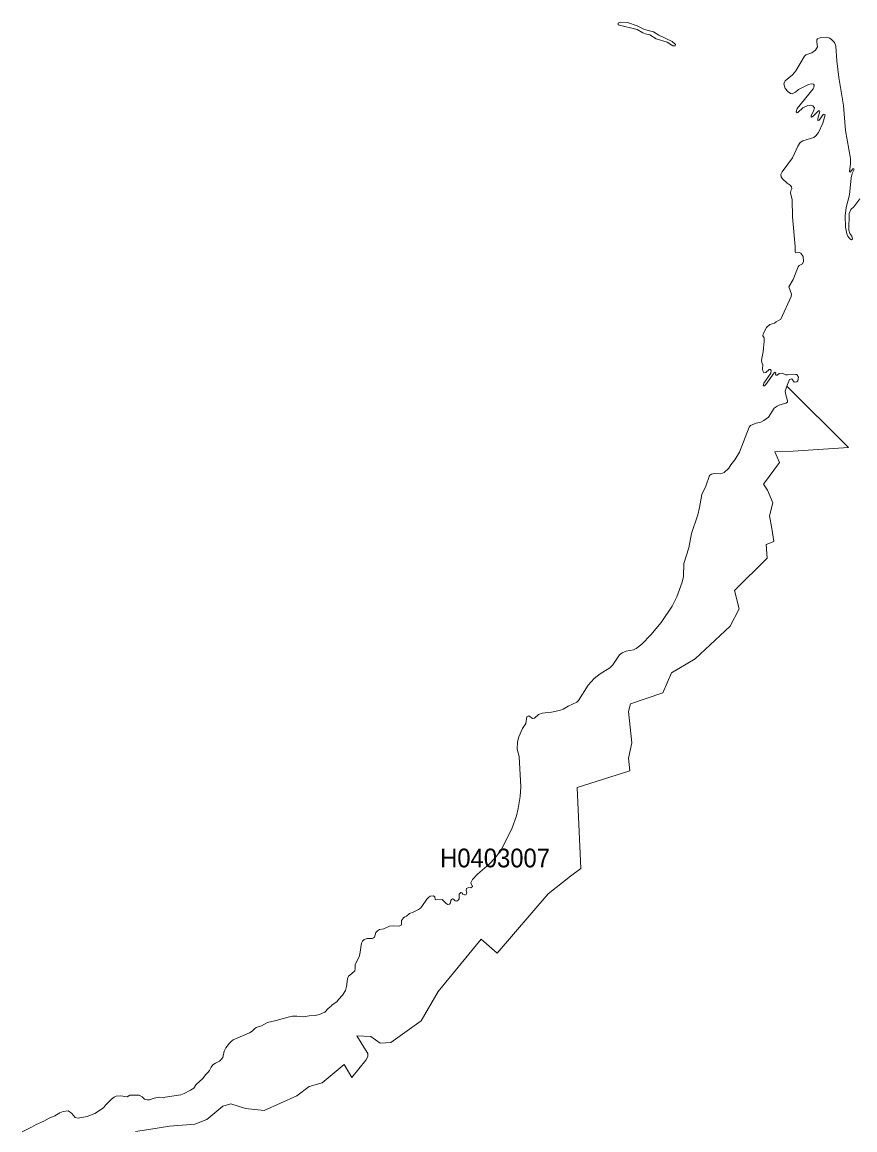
# Model space of a CAD drawing. Extents: x 369010 to 739155, y 6377141 to 6616555.
# Drawn here: x 410311 to 414756, y 6494241 to 6500155 of the extents above; entities that cross this region are included whole.
import ezdxf
from ezdxf.enums import TextEntityAlignment as Align

# ---------------------------------------------------------------- set-up
doc = ezdxf.new("R2010")
doc.units = 0
doc.header["$LTSCALE"] = 40
doc.layers.add('1', color=7, linetype='Continuous', lineweight=13)
doc.layers.add('2', color=7, linetype='Continuous')

msp = doc.modelspace()

# ---------------------------------------------------------------- linework, layer by layer
at = {"layer": '1'}
msp.add_lwpolyline([(413797.24, 6500028.2), (413799.73, 6500034.66), (413781.85, 6500051.7), (413709.36, 6500085.47), (413682.05, 6500103.18), (413633.73, 6500116.09), (413593.34, 6500135.45), (413542.53, 6500152.5), (413505.46, 6500154.81), (413491.89, 6500149.19), (413493.38, 6500140.41), (413593.34, 6500116.09), (413624.79, 6500097.55), (413644.15, 6500090.43), (413661.03, 6500087.95), (413694.96, 6500065.44), (413753.72, 6500047.57), (413785.16, 6500027.54)], close=True, dxfattribs=at)
for points in [[(414783.32, 6499212.27), (414751.21, 6499169.57), (414735.32, 6499154.34), (414726.71, 6499132.49), (414724.73, 6499044.12), (414730.02, 6499026.41), (414739.46, 6499012.67), (414744.42, 6498995.62), (414739.13, 6498991.98), (414730.35, 6498998.77), (414719.1, 6499012.67), (414714.14, 6499024.75), (414707.02, 6499060), (414704.37, 6499120.74), (414710.49, 6499166.09), (414727.71, 6499232.13), (414737.64, 6499322.82), (414742.93, 6499347.48), (414752.37, 6499367.84), (414750.38, 6499371.32), (414746.41, 6499371.15), (414731.51, 6499354.6), (414728.53, 6499356.42), (414733.5, 6499400.61), (414733.17, 6499427.09), (414705.86, 6499577.2), (414695.6, 6499709.77), (414671.44, 6499860.05), (414659.52, 6499948.43), (414654.22, 6500027.37), (414648.1, 6500045.91), (414630.06, 6500063.79), (414621.29, 6500069.08), (414604.24, 6500073.88), (414573.95, 6500072.39), (414557.73, 6500066.27), (414554.09, 6500059.65), (414553.27, 6500047.9), (414557.9, 6500022.91), (414546.15, 6500004.37), (414525.96, 6499990.47), (414495.5, 6499980.54), (414488.22, 6499973.09), (414441.38, 6499894.48), (414424.01, 6499873.29), (414384.45, 6499841.51), (414376.51, 6499824.63), (414383.95, 6499801.46), (414398.35, 6499784.58), (414412.42, 6499773.16), (414421.69, 6499772.83), (414439.07, 6499781.44), (414456.45, 6499794.84), (414509.41, 6499821.65), (414525.3, 6499825.79), (414536.55, 6499824.14), (414540.03, 6499818.84), (414538.2, 6499806.76), (414534.07, 6499798.15), (414449.33, 6499693.55), (414442.87, 6499676.18), (414444.2, 6499673.69), (414446.52, 6499671.21), (414452.14, 6499672.87), (414478.79, 6499697.36), (414505.27, 6499710.43), (414517.02, 6499711.59)], [(414517.02, 6499711.59), (414532.41, 6499708.61), (414540.85, 6499697.36), (414536.22, 6499679.98), (414522.65, 6499656.48), (414522.32, 6499649.03), (414524.14, 6499646.88), (414534.73, 6499653.5), (414561.54, 6499680.64), (414567.17, 6499680.64), (414569.48, 6499677.33), (414558.23, 6499640.26), (414558.23, 6499629.67), (414561.21, 6499629.17), (414566.01, 6499632.32), (414587.69, 6499662.6), (414591.33, 6499664.42), (414597.12, 6499660.29), (414586.2, 6499615.93), (414563.03, 6499565.78), (414547.97, 6499547.25), (414537.38, 6499539.8), (414479.29, 6499521.59), (414464.06, 6499512.16), (414451.32, 6499492.47), (414423.01, 6499431.23), (414368.89, 6499355.1), (414361.78, 6499341.03), (414363.27, 6499328.95), (414369.56, 6499318.36), (414394.22, 6499294.85), (414411.59, 6499284.43), (414418.38, 6499274.99), (414419.54, 6499264.4), (414414.9, 6499253.81), (414413.41, 6499243.22), (414422.19, 6499206.14), (414423.68, 6499115.94), (414438.41, 6498956.9), (414437.25, 6498930.41), (414439.23, 6498923.46), (414459.26, 6498925.45), (414468.2, 6498922.14), (414480.44, 6498902.78), (414483.09, 6498876.29), (414476.97, 6498864.71), (414459.26, 6498855.11), (414453.8, 6498847.99), (414426.32, 6498780.3), (414404.81, 6498742.24), (414417.55, 6498703.01), (414416.06, 6498690.76), (414361.61, 6498569.28), (414336.79, 6498555.22), (414328.18, 6498546.94), (414302.69, 6498539.99), (414284.98, 6498523.94), (414266.61, 6498491.33), (414265.29, 6498479.58), (414271.91, 6498468.99), (414272.24, 6498451.61), (414266.61, 6498395.01), (414258.67, 6498350.16), (414259.33, 6498338.41), (414265.45, 6498325.5), (414263.14, 6498304.31), (414264.3, 6498292.73), (414271.08, 6498282.8), (414281.67, 6498284.62), (414298.22, 6498300.51), (414305.84, 6498300.51), (414309.48, 6498294.88), (414307, 6498281.64), (414271.08, 6498227.19), (414267.61, 6498212.95), (414273.23, 6498212.46), (414282, 6498220.57), (414325.37, 6498283.29), (414331.16, 6498285.94), (414334.14, 6498284.78), (414333.48, 6498273.03), (414336.46, 6498272.21), (414333.81, 6498271.54), (414336.79, 6498269.56), (414342.41, 6498270.05), (414351.52, 6498279.32), (414368.07, 6498281.31), (414388.09, 6498272.54), (414397.53, 6498271.05), (414440.89, 6498274.52), (414447.51, 6498273.2), (414455.45, 6498260.12), (414452.31, 6498240.59), (414446.35, 6498233.64), (414433.11, 6498233.31), (414419.21, 6498250.03), (414406.96, 6498247.21), (414394.05, 6498210.8), (414394.22, 6498210.47), (414722.41, 6497883.93)], [(411296.48, 6494295.97), (411381.22, 6494366.97), (411425.24, 6494379.72), (411502.36, 6494354.23), (411602.16, 6494343.47), (411776.94, 6494422.58), (411843.3, 6494473.23), (411912.81, 6494492.09), (412029.99, 6494590.24), (412071.04, 6494520.56), (412146.34, 6494612.58), (412156.6, 6494633.1), (412156.6, 6494647.67), (412143.2, 6494667.53), (412097.68, 6494742.67), (412171.99, 6494738.53), (412221.81, 6494704.44), (412279.41, 6494707.25), (412441.27, 6494823.6), (412531.47, 6494978.68), (412762.18, 6495259.7), (412847.58, 6495184.4), (413118.51, 6495500.68), (413239, 6495596.17), (413294.11, 6495636.22), (413274.09, 6496068.02), (413554.45, 6496157.56), (413548.16, 6496225.25), (413566.37, 6496307.51), (413548.16, 6496475), (413558.75, 6496514.72), (413731.37, 6496574.47), (413778.21, 6496680.88), (413903.5, 6496755.53), (414091.18, 6496929.97), (414138.18, 6497022.32), (414113.85, 6497120.3), (414287.96, 6497293.41), (414283.33, 6497365.74), (414324.21, 6497381.3), (414313.62, 6497450.97), (414301.53, 6497519), (414318.25, 6497588.51), (414289.29, 6497656.03), (414268.1, 6497688.64), (414354.33, 6497803.66), (414328.51, 6497860.43), (414426.82, 6497864.73), (414722.41, 6497883.93), (414394.22, 6498210.47), (414394.05, 6498210.8)], [(414394.05, 6498210.8), (414384.45, 6498184.16), (414385.44, 6498172.41), (414397.69, 6498132.52), (414396.2, 6498125.57), (414387.43, 6498120.27), (414355.98, 6498111), (414340.92, 6498104.05), (414326.53, 6498093.63), (414294.75, 6498046.29), (414270.75, 6498028.09), (414254.86, 6498019.48), (414229.54, 6498013.36), (414198.92, 6498000.94), (414191.31, 6497992.01), (414140.33, 6497859.6), (414116.17, 6497817.4), (414094.16, 6497790.59), (414083.73, 6497774.37), (414058.74, 6497751.2), (414041.36, 6497743.25), (414005.78, 6497745.9), (413990.39, 6497741.93), (413980.13, 6497733.99), (413960.93, 6497678.05), (413939.08, 6497632.2), (413927.16, 6497563.19), (413917.73, 6497524.95), (413884.96, 6497425.32), (413870.56, 6497348.86), (413843.42, 6497264.62), (413840.77, 6497195.6), (413835.14, 6497164.98), (413806.84, 6497087.53), (413781.35, 6497036.88), (413722.44, 6496949.99), (413667.65, 6496883.13), (413619, 6496833.98), (413588.71, 6496811.63), (413573.98, 6496804.52), (413535.58, 6496796.24), (413513.24, 6496788.3), (413500.33, 6496777.37), (413463.75, 6496724.41), (413448.2, 6496707.86), (413396.39, 6496675.75), (413363.95, 6496649.93), (413332.67, 6496614.19), (413281.2, 6496532.92), (413271.77, 6496524.98), (413226.42, 6496503.79), (413199.94, 6496487.58), (413179.25, 6496479.63), (413136.88, 6496470.2), (413087.4, 6496464.9), (413067.37, 6496458.45), (413045.86, 6496438.92), (413035.76, 6496436.93), (413015.57, 6496451.66), (413005.8, 6496446.7), (412999.85, 6496410.78), (412982.8, 6496383.97), (412961.61, 6496338.62), (412955.49, 6496312.64), (412953.01, 6496273.74), (412963.6, 6496234.85), (412972.21, 6496072.82), (412968.73, 6496021.02), (412958.63, 6495956.31), (412949.2, 6495917.41), (412926.2, 6495852.54), (412882.34, 6495761.84), (412862.64, 6495727.75), (412835.5, 6495692.33), (412803.72, 6495659.39), (412741, 6495606.1), (412714.85, 6495577.47), (412706.9, 6495559.26), (412714.85, 6495539.4), (412705.91, 6495532.45), (412696.31, 6495534.44), (412686.55, 6495531.79), (412682.9, 6495528.65), (412680.59, 6495520.87), (412684.23, 6495504.98), (412680.92, 6495497.03), (412677.94, 6495495.38), (412672.31, 6495496.37), (412664.04, 6495499.02), (412658.91, 6495505.81), (412652.45, 6495507.63), (412644.18, 6495499.52), (412643.18, 6495474.03), (412639.54, 6495469.06), (412631.43, 6495462.61), (412622.5, 6495464.26), (412613.06, 6495473.37), (412608.1, 6495474.03), (412602.3, 6495470.39), (412598.99, 6495464.6)], [(414722.41, 6497883.93), (414426.82, 6497864.73), (414328.51, 6497860.43), (414354.33, 6497803.66), (414268.1, 6497688.64), (414289.29, 6497656.03), (414318.25, 6497588.51), (414301.53, 6497519), (414313.62, 6497450.97), (414324.21, 6497381.3), (414283.33, 6497365.74), (414287.96, 6497293.41), (414113.85, 6497120.3), (414138.18, 6497022.32), (414091.18, 6496929.97), (413903.5, 6496755.53), (413778.21, 6496680.88), (413731.37, 6496574.47), (413558.75, 6496514.72), (413548.16, 6496475), (413566.37, 6496307.51), (413548.16, 6496225.25), (413554.45, 6496157.56), (413274.09, 6496068.02), (413294.11, 6495636.22), (413239, 6495596.17), (413118.51, 6495500.68), (412847.58, 6495184.4), (412762.18, 6495259.7), (412531.47, 6494978.68), (412441.27, 6494823.6), (412279.41, 6494707.25), (412221.81, 6494704.44), (412171.99, 6494738.53), (412097.68, 6494742.67), (412143.2, 6494667.53), (412156.6, 6494647.67), (412156.6, 6494633.1), (412146.34, 6494612.58), (412071.04, 6494520.56), (412029.99, 6494590.24), (411912.81, 6494492.09), (411843.3, 6494473.23), (411776.94, 6494422.58), (411602.16, 6494343.47), (411502.36, 6494354.23), (411425.24, 6494379.72), (411381.22, 6494366.97), (411296.48, 6494295.97), (411232.92, 6494271.81), (411096.71, 6494260.55), (410987.81, 6494243.51), (410915.82, 6494232.09)], [(412598.99, 6495464.6), (412596.68, 6495452.18), (412591.55, 6495445.23), (412583.27, 6495444.9), (412575.16, 6495449.53), (412552.65, 6495470.39), (412519.39, 6495468.73), (412516.41, 6495470.72), (412514.75, 6495485.12), (412505.32, 6495490.74), (412489.6, 6495487.77), (412479.5, 6495481.81), (412470.73, 6495473.04), (412445.24, 6495434.14), (412436.63, 6495424.71), (412426.54, 6495417.26), (412399.07, 6495402.86), (412377.88, 6495395.58), (412362.16, 6495381.68), (412353.06, 6495378.37), (412345.94, 6495372.08), (412336.01, 6495359), (412336.67, 6495338.48), (412334.52, 6495332.85), (412323.93, 6495328.72), (412294.63, 6495330.7), (412271.13, 6495328.39), (412242.33, 6495314.65), (412218.83, 6495310.01), (412207.08, 6495303.89), (412198.97, 6495294.79), (412191.36, 6495269.63), (412185.57, 6495265.33), (412179.61, 6495263.34), (412152.46, 6495262.02), (412136.91, 6495256.89), (412127.97, 6495248.94), (412122.18, 6495237.19), (412113.57, 6495178.44), (412110.76, 6495166.69), (412088.75, 6495122.5), (412088.75, 6495100.98), (412085.93, 6495090.56), (412069.88, 6495073.51), (412052.83, 6495061.43), (412047.37, 6495047.86), (412042.4, 6495006.65), (412036.28, 6494984.8), (412020.56, 6494959.64), (411999.37, 6494936.64), (411990.77, 6494925.22), (411965.28, 6494908.67), (411961.64, 6494902.71), (411944.76, 6494888.97), (411926.55, 6494870.1), (411898.75, 6494856.37), (411875.25, 6494850.74), (411843.8, 6494848.92), (411813.18, 6494844.29), (411777.27, 6494848.26), (411753.77, 6494847.93), (411730.1, 6494843.29), (411667.37, 6494824.09), (411620.7, 6494814.83), (411588.76, 6494796.29), (411560.62, 6494787.52), (411550.53, 6494780.24), (411538.11, 6494768.49), (411523.71, 6494758.72), (411437.82, 6494721.15), (411428.38, 6494714.53), (411417.3, 6494703.44), (411398.59, 6494679.28), (411389.49, 6494661.07), (411382.04, 6494627.97), (411372.11, 6494614.73), (411363.67, 6494607.12), (411342.82, 6494597.69), (411329.08, 6494587.92), (411320.31, 6494576.17), (411311.04, 6494557.14), (411303.59, 6494548.03), (411288.86, 6494534.96), (411275.13, 6494514.44), (411240.21, 6494482.66), (411227.79, 6494463.79), (411208.93, 6494452.37), (411174.83, 6494434.99), (411157.29, 6494428.21), (411074.87, 6494415.8), (411063.12, 6494412.16), (411044.25, 6494414.8), (411032.5, 6494414.47), (411014.79, 6494410.5), (410991.29, 6494401.4), (410978.21, 6494400.74), (410963.48, 6494404.87), (410952.06, 6494416.46), (410935.84, 6494425.23), (410890.66, 6494426.55)], [(410890.66, 6494426.55), (410885.53, 6494425.56), (410871.13, 6494417.12), (410835.88, 6494422.91), (410812.38, 6494419.93), (410801.29, 6494415.8), (410786.89, 6494405.2), (410754.78, 6494371.94), (410744.03, 6494357.87), (410698.02, 6494327.58), (410656.8, 6494311.86), (410609.8, 6494303.09), (410594.08, 6494306.23), (410576.2, 6494327.58), (410566.94, 6494335.69), (410556.51, 6494341.65), (410530.03, 6494338.34), (410512.49, 6494331.72), (410485.01, 6494315.5), (410455.55, 6494303.09), (410426.92, 6494288.03), (410384.72, 6494268.99), (410360.88, 6494255.09), (410310.57, 6494230.27)], [(410915.82, 6494232.09), (410987.81, 6494243.51), (411096.71, 6494260.55), (411232.92, 6494271.81), (411296.48, 6494295.97)]]:
    msp.add_lwpolyline(points, dxfattribs=at)

# ---------------------------------------------------------------- texts
at = {"layer": '2', "width": 0.95}
msp.add_text('H0403007', height=100, dxfattribs=at).set_placement((412835.48, 6495642.33), align=Align.CENTER)

doc.saveas('drawing.dxf')
